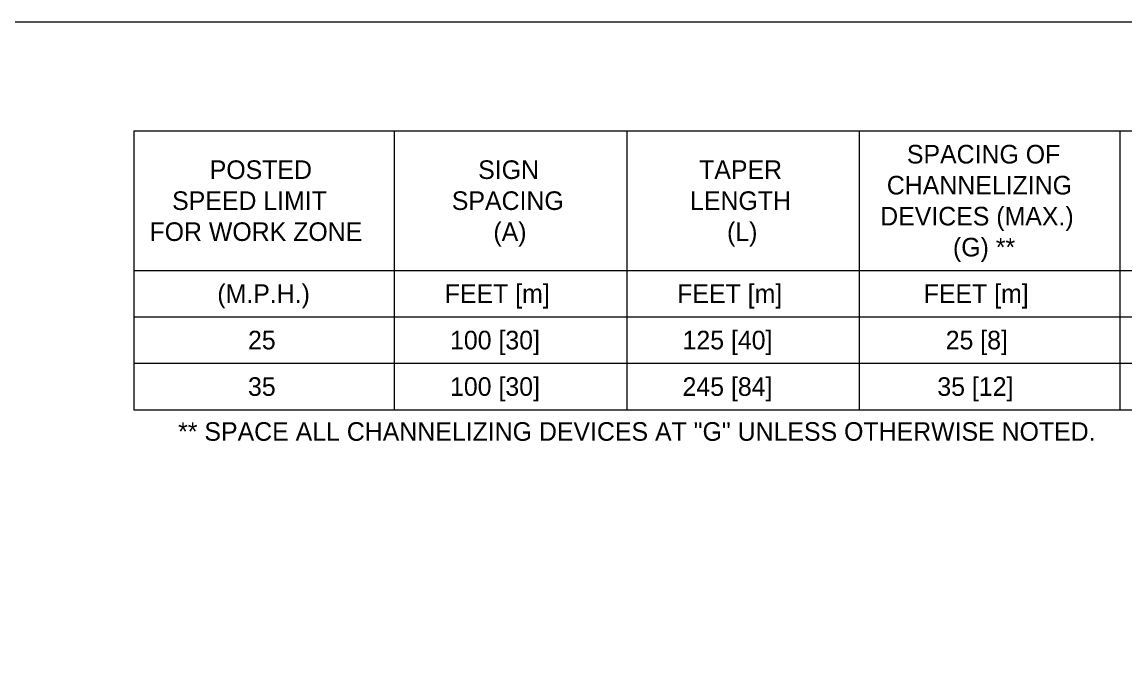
# Model space of a CAD drawing. Extents: x 49991.4 to 50021, y 49987.6 to 50011.4.
# Drawn here: x 50002.149 to 50005.707, y 50009.223 to 50011.263 of the extents above; entities that cross this region are included whole.
import ezdxf

# ---------------------------------------------------------------- set-up
doc = ezdxf.new("R2010")
doc.units = 0
doc.layers.add('Level 1', color=7, linetype='Continuous')
doc.layers.add('Level 2', color=7, linetype='Continuous')

msp = doc.modelspace()

# ---------------------------------------------------------------- linework, layer by layer
at = {"layer": 'Level 1'}
msp.add_lwpolyline([(50008.6146, 50011.2628), (50000.3356, 50011.2628), (50000.3356, 50000.0624), (50008.6146, 50000.0624)], close=True, dxfattribs=at)
at = {"layer": 'Level 2'}
for p, q in [((50002.5101, 50010.9113), (50006.4401, 50010.9113)), ((50002.5101, 50010.9113), (50002.5101, 50010.0113)), ((50003.3501, 50010.9113), (50003.3501, 50010.0113)), ((50004.1001, 50010.9113), (50004.1001, 50010.0113)), ((50004.8501, 50010.9113), (50004.8501, 50010.0113)), ((50005.6901, 50010.9113), (50005.6901, 50010.0113)), ((50002.5101, 50010.4613), (50006.4401, 50010.4613)), ((50002.5101, 50010.3113), (50006.4401, 50010.3113)), ((50002.5101, 50010.1613), (50006.4401, 50010.1613)), ((50002.5101, 50010.0113), (50006.4401, 50010.0113))]:
    msp.add_line(p, q, dxfattribs=at)

# ---------------------------------------------------------------- texts
for s, p in [('SPACING OF', (50005.0036, 50010.8063)), ('POSTED', (50002.7548, 50010.7563)), ('SIGN', (50003.6208, 50010.7563)), ('TAPER', (50004.3334, 50010.7563)), ('CHANNELIZING', (50004.9389, 50010.7063)), ('SPEED LIMIT', (50002.6335, 50010.6563)), ('SPACING', (50003.5357, 50010.6563)), ('LENGTH', (50004.3042, 50010.6563)), ('DEVICES (MAX.)', (50004.9175, 50010.6063)), ('FOR WORK ZONE', (50002.5605, 50010.5563)), ('(A)', (50003.6698, 50010.5563)), ('(L)', (50004.4235, 50010.5563)), ('(G) **', (50005.1522, 50010.5063)), ('(M.P.H.)', (50002.7794, 50010.3563)), ('FEET [m]', (50003.5128, 50010.3563)), ('FEET [m]', (50004.2628, 50010.3563)), ('FEET [m]', (50005.0578, 50010.3563)), ('25', (50002.8783, 50010.2063)), ('100 [30]', (50003.53, 50010.2063)), ('125 [40]', (50004.28, 50010.2063)), ('25 [8]', (50005.1288, 50010.2063)), ('35', (50002.8783, 50010.0563)), ('100 [30]', (50003.53, 50010.0563)), ('245 [84]', (50004.28, 50010.0563)), ('35 [12]', (50005.1019, 50010.0563)), ('** SPACE ALL CHANNELIZING DEVICES AT "G" UNLESS OTHERWISE NOTED.', (50002.6529, 50009.9113))]:
    msp.add_text(s, height=0.06, dxfattribs=at).set_placement(p)

doc.saveas('drawing.dxf')
